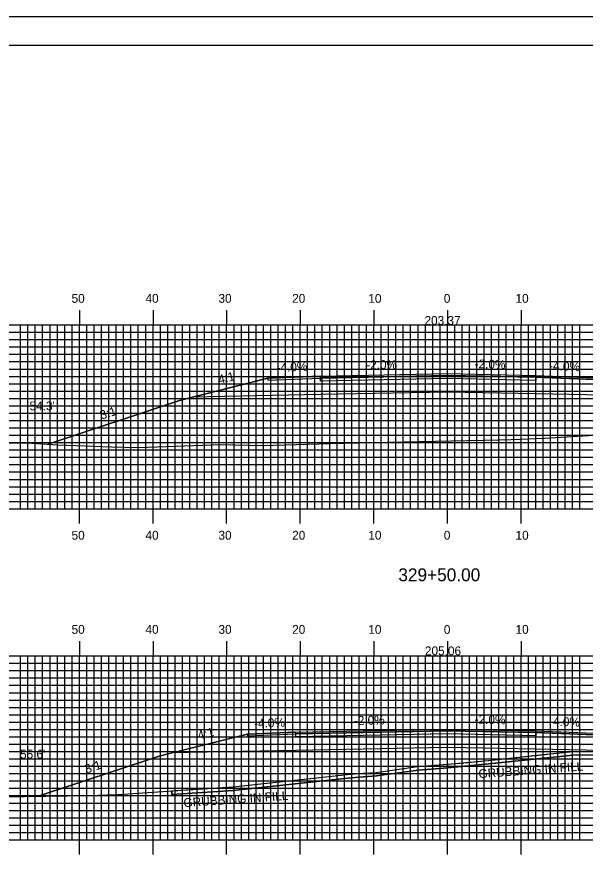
# Model space of a CAD drawing. Extents: x 1821998 to 1822342, y 442591 to 442811.
# Drawn here: x 1822105.8 to 1822183, y 442696.2 to 442810.5 of the extents above; entities that cross this region are included whole.
import ezdxf

# ---------------------------------------------------------------- set-up
doc = ezdxf.new("R2010")
doc.units = 0
for name, color, linetype in [('ANNOTATION', 7, 'Continuous'), ('BORDER', 7, 'Continuous'), ('D_Roadway_Centerline', 7, 'Continuous'), ('D_Roadway_Centerline_Text', 7, 'Continuous'), ('D_Roadway_Edge_Shoulder', 7, 'Continuous'), ('D_Roadway_Edge_TW', 7, 'Continuous'), ('D_Roadway_Pavement', 7, 'Continuous'), ('D_Roadway_SlopeLines', 7, 'Continuous'), ('D_Roadway_SubGrade', 7, 'Continuous'), ('D_Text_Standard', 7, 'Continuous'), ('GRUBBING IN FILL', 7, 'Continuous'), ('H_V ANNOTATION', 7, 'Continuous'), ('MAJOR', 7, 'Continuous'), ('MINOR', 7, 'Continuous'), ('PLOT BOUNDARY', 7, 'Continuous'), ('S_Roadway_Centerline', 7, 'Continuous')]:
    doc.layers.add(name, color=color, linetype=linetype)

msp = doc.modelspace()

# ---------------------------------------------------------------- linework, layer by layer
at = {"layer": 'BORDER'}
msp.add_lwpolyline([(1822014.66, 442596.67), (1822334.66, 442596.67), (1822334.66, 442806.67), (1822014.66, 442806.67)], close=True, dxfattribs=at)
at = {"layer": 'D_Roadway_Centerline'}
for points in [[(1822109.99, 442752.45), (1822127.87, 442758.41), (1822129.62, 442758.85), (1822139.87, 442761.41), (1822146.99, 442761.69), (1822164.26, 442762.04), (1822176.26, 442761.8), (1822184.26, 442761.48), (1822194.43, 442758.94), (1822210.54, 442754.91)], [(1822108.66, 442704.58), (1822125.09, 442710.05), (1822126.79, 442710.48), (1822137.09, 442713.05), (1822143.66, 442713.32), (1822164.26, 442713.73), (1822176.26, 442713.49), (1822184.26, 442713.17), (1822194.43, 442710.63), (1822198.43, 442709.63), (1822204.69, 442711.19), (1822205.94, 442711.48), (1822207.19, 442711.71), (1822208.44, 442711.89), (1822209.69, 442712.02)]]:
    msp.add_lwpolyline(points, dxfattribs=at)
at = {"layer": 'D_Roadway_Edge_Shoulder'}
for points in [[(1822146.99, 442761.69), (1822139.87, 442761.41), (1822139.87, 442761.16), (1822146.99, 442761.44)], [(1822176.26, 442761.8), (1822184.26, 442761.48), (1822184.26, 442761.23), (1822176.26, 442761.55)], [(1822143.66, 442713.32), (1822137.09, 442713.05), (1822137.09, 442712.8), (1822143.66, 442713.07)], [(1822176.26, 442713.49), (1822184.26, 442713.17), (1822184.26, 442712.92), (1822176.26, 442713.24)]]:
    msp.add_lwpolyline(points, close=True, dxfattribs=at)
at = {"layer": 'D_Roadway_Edge_TW'}
for points in [[(1822146.99, 442761.44), (1822146.99, 442761.69), (1822164.26, 442762.04), (1822176.26, 442761.8), (1822176.26, 442761.55), (1822164.26, 442761.79)], [(1822143.66, 442713.07), (1822143.66, 442713.32), (1822164.26, 442713.73), (1822176.26, 442713.49), (1822176.26, 442713.24), (1822164.26, 442713.48)]]:
    msp.add_lwpolyline(points, close=True, dxfattribs=at)
at = {"layer": 'D_Roadway_Pavement'}
for points in [[(1822146.99, 442761.03), (1822146.99, 442761.44), (1822164.26, 442761.79), (1822176.26, 442761.55), (1822176.26, 442761.13), (1822164.26, 442761.37)], [(1822143.66, 442712.65), (1822143.66, 442713.07), (1822164.26, 442713.48), (1822176.26, 442713.24), (1822176.26, 442712.82), (1822164.26, 442713.06)]]:
    msp.add_lwpolyline(points, close=True, dxfattribs=at)
at = {"layer": 'D_Roadway_SlopeLines'}
for points in [[(1822139.87, 442761.41), (1822127.87, 442758.41), (1822109.99, 442752.45)], [(1822137.09, 442713.05), (1822125.09, 442710.05), (1822108.66, 442704.58)]]:
    msp.add_lwpolyline(points, dxfattribs=at)
at = {"layer": 'D_Roadway_SubGrade'}
for points in [[(1822146.99, 442759.19), (1822129.62, 442758.85), (1822139.87, 442761.41), (1822139.87, 442761.16), (1822146.99, 442761.44), (1822164.26, 442761.79), (1822176.26, 442761.55), (1822184.26, 442761.23), (1822184.26, 442761.48), (1822194.43, 442758.94), (1822176.26, 442759.3), (1822164.26, 442759.54)], [(1822143.66, 442710.82), (1822126.79, 442710.48), (1822137.09, 442713.05), (1822137.09, 442712.8), (1822143.66, 442713.07), (1822164.26, 442713.48), (1822176.26, 442713.24), (1822184.26, 442712.92), (1822184.26, 442713.17), (1822194.43, 442710.63), (1822176.26, 442710.99), (1822164.26, 442711.23)]]:
    msp.add_lwpolyline(points, close=True, dxfattribs=at)
at = {"layer": 'GRUBBING IN FILL'}
msp.add_line((1822126.79, 442705.32), (1822126.79, 442704.82), dxfattribs=at)
msp.add_line((1822126.79, 442705.32), (1822126.79, 442704.82), dxfattribs=at)
msp.add_lwpolyline([(1822126.79, 442704.82), (1822135.16, 442705.37), (1822151.14, 442707.08), (1822154.61, 442707.35), (1822160.26, 442708.12), (1822163.8, 442708.4), (1822170.35, 442709.02), (1822181.73, 442710.2), (1822186.27, 442710.15), (1822192.98, 442710.65)], dxfattribs=at)
msp.add_lwpolyline([(1822126.79, 442704.82), (1822135.16, 442705.37), (1822151.14, 442707.08), (1822154.61, 442707.35), (1822160.26, 442708.12), (1822163.8, 442708.4), (1822170.35, 442709.02), (1822181.73, 442710.2), (1822186.27, 442710.15), (1822192.98, 442710.65)], dxfattribs=at)
for points in [[(1822164.26, 442708.94), (1822167.03, 442709.2), (1822170.3, 442709.51), (1822176, 442710.11), (1822181.71, 442710.7), (1822183.98, 442710.68), (1822186.26, 442710.65), (1822187.71, 442710.76), (1822192.98, 442710.65), (1822189.12, 442710.36), (1822186.27, 442710.15), (1822184, 442710.18), (1822181.73, 442710.2), (1822176.04, 442709.61), (1822170.35, 442709.02), (1822164.26, 442708.44)], [(1822164.26, 442708.94), (1822167.03, 442709.2), (1822170.3, 442709.51), (1822176, 442710.11), (1822181.71, 442710.7), (1822183.98, 442710.68), (1822186.26, 442710.65), (1822187.71, 442710.76), (1822192.98, 442710.65), (1822189.12, 442710.36), (1822186.27, 442710.15), (1822184, 442710.18), (1822181.73, 442710.2), (1822176.04, 442709.61), (1822170.35, 442709.02), (1822164.26, 442708.44)], [(1822126.79, 442705.32), (1822127.29, 442705.35), (1822135.11, 442705.87), (1822143.1, 442706.73), (1822151.09, 442707.58), (1822152.83, 442707.71), (1822154.56, 442707.84), (1822160.21, 442708.62), (1822164.26, 442708.94), (1822164.26, 442708.44), (1822162.03, 442708.26), (1822160.26, 442708.12), (1822157.44, 442707.73), (1822154.61, 442707.35), (1822152.87, 442707.21), (1822151.14, 442707.08), (1822143.15, 442706.23), (1822135.16, 442705.37), (1822130.97, 442705.1), (1822126.79, 442704.82)], [(1822126.79, 442705.32), (1822127.29, 442705.35), (1822135.11, 442705.87), (1822143.1, 442706.73), (1822151.09, 442707.58), (1822152.83, 442707.71), (1822154.56, 442707.84), (1822160.21, 442708.62), (1822164.26, 442708.94), (1822164.26, 442708.44), (1822162.03, 442708.26), (1822160.26, 442708.12), (1822157.44, 442707.73), (1822154.61, 442707.35), (1822152.87, 442707.21), (1822151.14, 442707.08), (1822143.15, 442706.23), (1822135.16, 442705.37), (1822130.97, 442705.1), (1822126.79, 442704.82)]]:
    msp.add_lwpolyline(points, close=True, dxfattribs=at)
at = {"layer": 'MAJOR'}
for p, q in [((1822114.26, 442770.67), (1822114.26, 442768.67)), ((1822124.26, 442770.67), (1822124.26, 442768.67)), ((1822134.26, 442770.67), (1822134.26, 442768.67)), ((1822144.26, 442770.67), (1822144.26, 442768.67)), ((1822154.26, 442770.67), (1822154.26, 442768.67)), ((1822164.26, 442770.67), (1822164.26, 442768.67)), ((1822174.26, 442770.67), (1822174.26, 442768.67)), ((1822024.26, 442768.67), (1822304.26, 442768.67)), ((1822024.26, 442768.67), (1822304.26, 442768.67)), ((1822114.26, 442743.67), (1822114.26, 442768.67)), ((1822124.26, 442743.67), (1822124.26, 442768.67)), ((1822134.26, 442743.67), (1822134.26, 442768.67)), ((1822144.26, 442743.67), (1822144.26, 442768.67)), ((1822154.26, 442743.67), (1822154.26, 442768.67)), ((1822164.26, 442743.67), (1822164.26, 442768.67)), ((1822174.26, 442743.67), (1822174.26, 442768.67)), ((1822024.26, 442763.67), (1822304.26, 442763.67)), ((1822024.26, 442758.67), (1822304.26, 442758.67)), ((1822024.26, 442753.67), (1822304.26, 442753.67)), ((1822024.26, 442748.67), (1822304.26, 442748.67)), ((1822024.26, 442743.67), (1822304.26, 442743.67)), ((1822024.26, 442743.67), (1822304.26, 442743.67)), ((1822114.26, 442741.66), (1822114.26, 442743.67)), ((1822124.26, 442741.66), (1822124.26, 442743.67)), ((1822134.26, 442741.66), (1822134.26, 442743.67)), ((1822144.26, 442741.66), (1822144.26, 442743.67)), ((1822154.26, 442741.66), (1822154.26, 442743.67)), ((1822164.26, 442741.66), (1822164.26, 442743.67)), ((1822174.26, 442741.66), (1822174.26, 442743.67)), ((1822114.26, 442725.67), (1822114.26, 442723.67)), ((1822124.26, 442725.67), (1822124.26, 442723.67)), ((1822134.26, 442725.67), (1822134.26, 442723.67)), ((1822144.26, 442725.67), (1822144.26, 442723.67)), ((1822154.26, 442725.67), (1822154.26, 442723.67)), ((1822164.26, 442725.67), (1822164.26, 442723.67)), ((1822174.26, 442725.67), (1822174.26, 442723.67)), ((1822024.26, 442723.67), (1822304.26, 442723.67)), ((1822024.26, 442723.67), (1822304.26, 442723.67)), ((1822114.26, 442698.67), (1822114.26, 442723.67)), ((1822124.26, 442698.67), (1822124.26, 442723.67)), ((1822134.26, 442698.67), (1822134.26, 442723.67)), ((1822144.26, 442698.67), (1822144.26, 442723.67)), ((1822154.26, 442698.67), (1822154.26, 442723.67)), ((1822164.26, 442698.67), (1822164.26, 442723.67)), ((1822174.26, 442698.67), (1822174.26, 442723.67)), ((1822024.26, 442718.67), (1822304.26, 442718.67)), ((1822024.26, 442713.67), (1822304.26, 442713.67)), ((1822024.26, 442708.67), (1822304.26, 442708.67)), ((1822024.26, 442703.67), (1822304.26, 442703.67)), ((1822024.26, 442698.67), (1822304.26, 442698.67)), ((1822024.26, 442698.67), (1822304.26, 442698.67)), ((1822114.26, 442696.66), (1822114.26, 442698.67)), ((1822124.26, 442696.66), (1822124.26, 442698.67)), ((1822134.26, 442696.66), (1822134.26, 442698.67)), ((1822144.26, 442696.66), (1822144.26, 442698.67)), ((1822154.26, 442696.66), (1822154.26, 442698.67)), ((1822164.26, 442696.66), (1822164.26, 442698.67)), ((1822174.26, 442696.66), (1822174.26, 442698.67))]:
    msp.add_line(p, q, dxfattribs=at)
at = {"layer": 'MINOR'}
for p, q in [((1822024.26, 442767.67), (1822304.26, 442767.67)), ((1822106.26, 442743.67), (1822106.26, 442768.67)), ((1822107.26, 442743.67), (1822107.26, 442768.67)), ((1822108.26, 442743.67), (1822108.26, 442768.67)), ((1822109.26, 442743.67), (1822109.26, 442768.67)), ((1822110.26, 442743.67), (1822110.26, 442768.67)), ((1822111.26, 442743.67), (1822111.26, 442768.67)), ((1822112.26, 442743.67), (1822112.26, 442768.67)), ((1822113.26, 442743.67), (1822113.26, 442768.67)), ((1822115.26, 442743.67), (1822115.26, 442768.67)), ((1822116.26, 442743.67), (1822116.26, 442768.67)), ((1822117.26, 442743.67), (1822117.26, 442768.67)), ((1822118.26, 442743.67), (1822118.26, 442768.67)), ((1822119.26, 442743.67), (1822119.26, 442768.67)), ((1822120.26, 442743.67), (1822120.26, 442768.67)), ((1822121.26, 442743.67), (1822121.26, 442768.67)), ((1822122.26, 442743.67), (1822122.26, 442768.67)), ((1822123.26, 442743.67), (1822123.26, 442768.67)), ((1822125.26, 442743.67), (1822125.26, 442768.67)), ((1822126.26, 442743.67), (1822126.26, 442768.67)), ((1822127.26, 442743.67), (1822127.26, 442768.67)), ((1822128.26, 442743.67), (1822128.26, 442768.67)), ((1822129.26, 442743.67), (1822129.26, 442768.67)), ((1822130.26, 442743.67), (1822130.26, 442768.67)), ((1822131.26, 442743.67), (1822131.26, 442768.67)), ((1822132.26, 442743.67), (1822132.26, 442768.67)), ((1822133.26, 442743.67), (1822133.26, 442768.67)), ((1822135.26, 442743.67), (1822135.26, 442768.67)), ((1822136.26, 442743.67), (1822136.26, 442768.67)), ((1822137.26, 442743.67), (1822137.26, 442768.67)), ((1822138.26, 442743.67), (1822138.26, 442768.67)), ((1822139.26, 442743.67), (1822139.26, 442768.67)), ((1822140.26, 442743.67), (1822140.26, 442768.67)), ((1822141.26, 442743.67), (1822141.26, 442768.67)), ((1822142.26, 442743.67), (1822142.26, 442768.67)), ((1822143.26, 442743.67), (1822143.26, 442768.67)), ((1822145.26, 442743.67), (1822145.26, 442768.67)), ((1822146.26, 442743.67), (1822146.26, 442768.67)), ((1822147.26, 442743.67), (1822147.26, 442768.67)), ((1822148.26, 442743.67), (1822148.26, 442768.67)), ((1822149.26, 442743.67), (1822149.26, 442768.67)), ((1822150.26, 442743.67), (1822150.26, 442768.67)), ((1822151.26, 442743.67), (1822151.26, 442768.67)), ((1822152.26, 442743.67), (1822152.26, 442768.67)), ((1822153.26, 442743.67), (1822153.26, 442768.67)), ((1822155.26, 442743.67), (1822155.26, 442768.67)), ((1822156.26, 442743.67), (1822156.26, 442768.67)), ((1822157.26, 442743.67), (1822157.26, 442768.67)), ((1822158.26, 442743.67), (1822158.26, 442768.67)), ((1822159.26, 442743.67), (1822159.26, 442768.67)), ((1822160.26, 442743.67), (1822160.26, 442768.67)), ((1822161.26, 442743.67), (1822161.26, 442768.67)), ((1822162.26, 442743.67), (1822162.26, 442768.67)), ((1822163.26, 442743.67), (1822163.26, 442768.67)), ((1822165.26, 442743.67), (1822165.26, 442768.67)), ((1822166.26, 442743.67), (1822166.26, 442768.67)), ((1822167.26, 442743.67), (1822167.26, 442768.67)), ((1822168.26, 442743.67), (1822168.26, 442768.67)), ((1822169.26, 442743.67), (1822169.26, 442768.67)), ((1822170.26, 442743.67), (1822170.26, 442768.67)), ((1822171.26, 442743.67), (1822171.26, 442768.67)), ((1822172.26, 442743.67), (1822172.26, 442768.67)), ((1822173.26, 442743.67), (1822173.26, 442768.67)), ((1822175.26, 442743.67), (1822175.26, 442768.67)), ((1822176.26, 442743.67), (1822176.26, 442768.67)), ((1822177.26, 442743.67), (1822177.26, 442768.67)), ((1822178.26, 442743.67), (1822178.26, 442768.67)), ((1822179.26, 442743.67), (1822179.26, 442768.67)), ((1822180.26, 442743.67), (1822180.26, 442768.67)), ((1822181.26, 442743.67), (1822181.26, 442768.67)), ((1822182.26, 442743.67), (1822182.26, 442768.67)), ((1822024.26, 442766.67), (1822304.26, 442766.67)), ((1822024.26, 442765.67), (1822304.26, 442765.67)), ((1822024.26, 442764.67), (1822304.26, 442764.67)), ((1822024.26, 442762.67), (1822304.26, 442762.67)), ((1822024.26, 442761.67), (1822304.26, 442761.67)), ((1822024.26, 442760.67), (1822304.26, 442760.67)), ((1822024.26, 442759.67), (1822304.26, 442759.67)), ((1822024.26, 442757.67), (1822304.26, 442757.67)), ((1822024.26, 442756.67), (1822304.26, 442756.67)), ((1822024.26, 442755.67), (1822304.26, 442755.67)), ((1822024.26, 442754.67), (1822304.26, 442754.67)), ((1822024.26, 442752.67), (1822304.26, 442752.67)), ((1822024.26, 442751.67), (1822304.26, 442751.67)), ((1822024.26, 442750.67), (1822304.26, 442750.67)), ((1822024.26, 442749.67), (1822304.26, 442749.67)), ((1822024.26, 442747.67), (1822304.26, 442747.67)), ((1822024.26, 442746.67), (1822304.26, 442746.67)), ((1822024.26, 442745.67), (1822304.26, 442745.67)), ((1822024.26, 442744.67), (1822304.26, 442744.67)), ((1822106.26, 442698.67), (1822106.26, 442723.67)), ((1822107.26, 442698.67), (1822107.26, 442723.67)), ((1822108.26, 442698.67), (1822108.26, 442723.67)), ((1822109.26, 442698.67), (1822109.26, 442723.67)), ((1822110.26, 442698.67), (1822110.26, 442723.67)), ((1822111.26, 442698.67), (1822111.26, 442723.67)), ((1822112.26, 442698.67), (1822112.26, 442723.67)), ((1822113.26, 442698.67), (1822113.26, 442723.67)), ((1822115.26, 442698.67), (1822115.26, 442723.67)), ((1822116.26, 442698.67), (1822116.26, 442723.67)), ((1822117.26, 442698.67), (1822117.26, 442723.67)), ((1822118.26, 442698.67), (1822118.26, 442723.67)), ((1822119.26, 442698.67), (1822119.26, 442723.67)), ((1822120.26, 442698.67), (1822120.26, 442723.67)), ((1822121.26, 442698.67), (1822121.26, 442723.67)), ((1822122.26, 442698.67), (1822122.26, 442723.67)), ((1822123.26, 442698.67), (1822123.26, 442723.67)), ((1822125.26, 442698.67), (1822125.26, 442723.67)), ((1822126.26, 442698.67), (1822126.26, 442723.67)), ((1822127.26, 442698.67), (1822127.26, 442723.67)), ((1822128.26, 442698.67), (1822128.26, 442723.67)), ((1822129.26, 442698.67), (1822129.26, 442723.67)), ((1822130.26, 442698.67), (1822130.26, 442723.67)), ((1822131.26, 442698.67), (1822131.26, 442723.67)), ((1822132.26, 442698.67), (1822132.26, 442723.67)), ((1822133.26, 442698.67), (1822133.26, 442723.67)), ((1822135.26, 442698.67), (1822135.26, 442723.67)), ((1822136.26, 442698.67), (1822136.26, 442723.67)), ((1822137.26, 442698.67), (1822137.26, 442723.67)), ((1822138.26, 442698.67), (1822138.26, 442723.67)), ((1822139.26, 442698.67), (1822139.26, 442723.67)), ((1822140.26, 442698.67), (1822140.26, 442723.67)), ((1822141.26, 442698.67), (1822141.26, 442723.67)), ((1822142.26, 442698.67), (1822142.26, 442723.67)), ((1822143.26, 442698.67), (1822143.26, 442723.67)), ((1822145.26, 442698.67), (1822145.26, 442723.67)), ((1822146.26, 442698.67), (1822146.26, 442723.67)), ((1822147.26, 442698.67), (1822147.26, 442723.67)), ((1822148.26, 442698.67), (1822148.26, 442723.67)), ((1822149.26, 442698.67), (1822149.26, 442723.67)), ((1822150.26, 442698.67), (1822150.26, 442723.67)), ((1822151.26, 442698.67), (1822151.26, 442723.67)), ((1822152.26, 442698.67), (1822152.26, 442723.67)), ((1822153.26, 442698.67), (1822153.26, 442723.67)), ((1822155.26, 442698.67), (1822155.26, 442723.67)), ((1822156.26, 442698.67), (1822156.26, 442723.67)), ((1822157.26, 442698.67), (1822157.26, 442723.67)), ((1822158.26, 442698.67), (1822158.26, 442723.67)), ((1822159.26, 442698.67), (1822159.26, 442723.67)), ((1822160.26, 442698.67), (1822160.26, 442723.67)), ((1822161.26, 442698.67), (1822161.26, 442723.67)), ((1822162.26, 442698.67), (1822162.26, 442723.67)), ((1822163.26, 442698.67), (1822163.26, 442723.67)), ((1822165.26, 442698.67), (1822165.26, 442723.67)), ((1822166.26, 442698.67), (1822166.26, 442723.67)), ((1822167.26, 442698.67), (1822167.26, 442723.67)), ((1822168.26, 442698.67), (1822168.26, 442723.67)), ((1822169.26, 442698.67), (1822169.26, 442723.67)), ((1822170.26, 442698.67), (1822170.26, 442723.67)), ((1822171.26, 442698.67), (1822171.26, 442723.67)), ((1822172.26, 442698.67), (1822172.26, 442723.67)), ((1822173.26, 442698.67), (1822173.26, 442723.67)), ((1822175.26, 442698.67), (1822175.26, 442723.67)), ((1822176.26, 442698.67), (1822176.26, 442723.67)), ((1822177.26, 442698.67), (1822177.26, 442723.67)), ((1822178.26, 442698.67), (1822178.26, 442723.67)), ((1822179.26, 442698.67), (1822179.26, 442723.67)), ((1822180.26, 442698.67), (1822180.26, 442723.67)), ((1822181.26, 442698.67), (1822181.26, 442723.67)), ((1822182.26, 442698.67), (1822182.26, 442723.67)), ((1822024.26, 442722.67), (1822304.26, 442722.67)), ((1822024.26, 442721.67), (1822304.26, 442721.67)), ((1822024.26, 442720.67), (1822304.26, 442720.67)), ((1822024.26, 442719.67), (1822304.26, 442719.67)), ((1822024.26, 442717.67), (1822304.26, 442717.67)), ((1822024.26, 442716.67), (1822304.26, 442716.67)), ((1822024.26, 442715.67), (1822304.26, 442715.67)), ((1822024.26, 442714.67), (1822304.26, 442714.67)), ((1822024.26, 442712.67), (1822304.26, 442712.67)), ((1822024.26, 442711.67), (1822304.26, 442711.67)), ((1822024.26, 442710.67), (1822304.26, 442710.67)), ((1822024.26, 442709.67), (1822304.26, 442709.67)), ((1822024.26, 442707.67), (1822304.26, 442707.67)), ((1822024.26, 442706.67), (1822304.26, 442706.67)), ((1822024.26, 442705.67), (1822304.26, 442705.67)), ((1822024.26, 442704.67), (1822304.26, 442704.67)), ((1822024.26, 442702.67), (1822304.26, 442702.67)), ((1822024.26, 442701.67), (1822304.26, 442701.67)), ((1822024.26, 442700.67), (1822304.26, 442700.67)), ((1822024.26, 442699.67), (1822304.26, 442699.67))]:
    msp.add_line(p, q, dxfattribs=at)
at = {"layer": 'PLOT BOUNDARY'}
msp.add_lwpolyline([(1821998.47, 442590.55), (1822338.47, 442590.55), (1822338.47, 442810.55), (1821998.47, 442810.55)], close=True, dxfattribs=at)
at = {"layer": 'S_Roadway_Centerline'}
for points in [[(1822096.56, 442752.9), (1822105.84, 442752.59), (1822107, 442752.63), (1822111.32, 442752.37), (1822118.63, 442752.11), (1822122.29, 442751.99), (1822133.52, 442752.41), (1822139.13, 442752.27), (1822148.35, 442752.53), (1822156.06, 442752.71), (1822171.39, 442753.04), (1822172.93, 442753.09), (1822177.45, 442753.28), (1822187.17, 442753.85), (1822189.53, 442753.97), (1822194.17, 442754.19), (1822206.35, 442754.73), (1822217.52, 442755.2), (1822223.32, 442755.6), (1822226.56, 442755.71), (1822241.04, 442756.07)], [(1822103.88, 442704.49), (1822115.53, 442704.7), (1822118.02, 442704.79), (1822118.53, 442704.8), (1822119.46, 442704.83), (1822135.11, 442705.87), (1822151.09, 442707.58), (1822154.56, 442707.84), (1822160.21, 442708.62), (1822163.76, 442708.9), (1822170.3, 442709.51), (1822181.71, 442710.7), (1822186.26, 442710.65), (1822193.2, 442711.17), (1822198.44, 442711.36), (1822202.91, 442711.46), (1822211.65, 442712.18), (1822220.15, 442712.54), (1822234.11, 442712.9)]]:
    msp.add_lwpolyline(points, dxfattribs=at)

# ---------------------------------------------------------------- texts
at = {"layer": 'ANNOTATION'}
for s, rotation, p in [('-4.0%', 2.2906, (1822141.06, 442762.26)), ('-2.0%', 1.1458, (1822153.23, 442762.62)), ('-2.0%', 358.8542, (1822167.94, 442762.77)), ('-4.0%', 357.7094, (1822178.05, 442762.53)), ('4:1', 14.0362, (1822133.28, 442760.62)), ('3:1', 18.4348, (1822117.27, 442755.78)), ('-4.0%', 2.2906, (1822138.01, 442713.89)), ('-2.0%', 1.1458, (1822151.56, 442714.28)), ('-2.0%', 358.8542, (1822167.94, 442714.46)), ('-4.0%', 357.7094, (1822178.05, 442714.22)), ('4:1', 14.0362, (1822130.48, 442712.26)), ('3:1', 18.4348, (1822115.22, 442707.67))]:
    msp.add_text(s, height=1.2, rotation=rotation, dxfattribs=at).set_placement(p)
at = {"layer": 'D_Roadway_Centerline'}
for s, p in [('C', (1822164.25, 442762.04)), ('L', (1822164.26, 442762.03)), ('C', (1822164.25, 442713.73)), ('L', (1822164.26, 442713.72))]:
    msp.add_text(s, height=0.0146, dxfattribs=at).set_placement(p)
at = {"layer": 'D_Roadway_Centerline_Text'}
for s, p in [('203.37', (1822161.14, 442768.67)), ('205.06', (1822161.2, 442723.76))]:
    msp.add_text(s, height=1.2, dxfattribs=at).set_placement(p)
at = {"layer": 'D_Text_Standard'}
for s, p in [("54.3'", (1822107.48, 442757.05)), ("55.6'", (1822106.19, 442709.71))]:
    msp.add_text(s, height=1.2, dxfattribs=at).set_placement(p)
at = {"layer": 'GRUBBING IN FILL'}
for rotation, p in [(4.2341, (1822168.52, 442707.04)), (4.0304, (1822128.44, 442703.1))]:
    msp.add_text('GRUBBING IN FILL', height=1.2, rotation=rotation, dxfattribs=at).set_placement(p)
at = {"layer": 'H_V ANNOTATION'}
for s, height, p in [('50', 1.2, (1822113.19, 442771.67)), ('40', 1.2, (1822123.23, 442771.67)), ('30', 1.2, (1822133.15, 442771.67)), ('20', 1.2, (1822143.16, 442771.67)), ('10', 1.2, (1822153.51, 442771.67)), ('0', 1.2, (1822163.77, 442771.67)), ('10', 1.2, (1822173.51, 442771.67)), ('50', 1.2, (1822113.19, 442739.47)), ('40', 1.2, (1822123.23, 442739.47)), ('30', 1.2, (1822133.15, 442739.47)), ('20', 1.2, (1822143.16, 442739.47)), ('10', 1.2, (1822153.51, 442739.47)), ('0', 1.2, (1822163.77, 442739.47)), ('10', 1.2, (1822173.51, 442739.47)), ('329+50.00', 1.75, (1822157.59, 442733.82)), ('50', 1.2, (1822113.19, 442726.67)), ('40', 1.2, (1822123.23, 442726.67)), ('30', 1.2, (1822133.15, 442726.67)), ('20', 1.2, (1822143.16, 442726.67)), ('10', 1.2, (1822153.51, 442726.67)), ('0', 1.2, (1822163.77, 442726.67)), ('10', 1.2, (1822173.51, 442726.67))]:
    msp.add_text(s, height=height, dxfattribs=at).set_placement(p)

doc.saveas('drawing.dxf')
